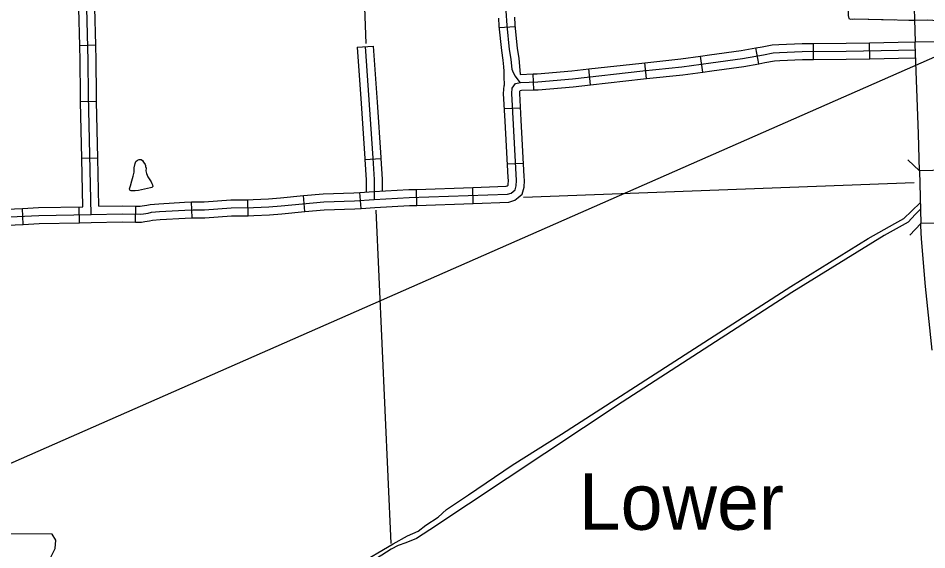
# Model space of a CAD drawing. Extents: x -5566 to 1759129, y -3726 to 731467.
# Drawn here: x -4760.4 to -4695.8, y 330.8 to 368.7 of the extents above; entities that cross this region are included whole.
import ezdxf

# ---------------------------------------------------------------- set-up
doc = ezdxf.new("R2010")
doc.units = 0
doc.layers.add('Default', color=7, linetype='Continuous')

msp = doc.modelspace()

# ---------------------------------------------------------------- linework, layer by layer
at = {"layer": 'Default'}
for p, q in [((-4726.234, 367.988), (-4725.097, 368.065)), ((-4754.916, 366.731), (-4756.055, 366.7)), ((-4736.317, 366.594), (-4735.18, 366.671)), ((-4707.76, 365.42), (-4707.965, 366.541)), ((-4703.872, 365.727), (-4703.877, 366.866)), ((-4699.854, 365.768), (-4699.875, 366.907)), ((-4711.748, 364.825), (-4711.907, 365.953)), ((-4715.75, 364.357), (-4715.869, 365.49)), ((-4723.77, 363.552), (-4723.805, 364.691)), ((-4719.731, 363.911), (-4719.858, 365.044)), ((-4754.859, 362.719), (-4755.997, 362.695)), ((-4724.71, 362.266), (-4725.848, 362.204)), ((-4754.774, 358.71), (-4755.913, 358.686)), ((-4735.774, 358.594), (-4734.637, 358.67)), ((-4724.496, 358.323), (-4725.634, 358.261)), ((-4736.053, 355.126), (-4736.136, 356.262)), ((-4732.071, 355.342), (-4732.111, 356.48)), ((-4728.064, 355.481), (-4728.103, 356.619)), ((-4748.074, 354.453), (-4748.121, 355.591)), ((-4744.085, 354.605), (-4744.102, 355.744)), ((-4740.041, 354.899), (-4740.15, 356.032)), ((-4760.08, 353.99), (-4760.132, 355.128)), ((-4756.086, 354.102), (-4756.11, 355.241)), ((-4752.102, 354.153), (-4752.077, 355.292))]:
    msp.add_line(p, q, dxfattribs=at)
for points in [[(-4813.973, 313.686), (-4397.101, 497.071), (-4397.101, 497.071)], [(-4755.259, 354.689), (-4755.438, 363.186), (-4755.457, 365.645), (-4755.557, 369.37), (-4755.723, 373.616), (-4756.249, 384.751), (-4756.683, 394.816), (-4756.724, 396.754), (-4756.875, 400.091), (-4757.762, 416.192), (-4757.786, 416.771)], [(-4736.745, 395.069), (-4735.714, 366.864)], [(-4702.309, 378.817), (-4702.105, 377.962), (-4701.846, 376.435), (-4701.707, 375.07), (-4701.5, 373.054), (-4701.416, 369.745), (-4701.392, 368.841), (-4701.36, 368.633), (-4701.242, 368.588), (-4700.92, 368.602), (-4696.883, 368.523), (-4695.733, 368.545), (-4695.387, 368.526), (-4695.122, 368.462), (-4694.828, 368.457), (-4692.797, 368.529), (-4679.95, 367.895)], [(-4756.055, 366.7), (-4756.126, 369.351), (-4756.179, 370.701)], [(-4754.916, 366.731), (-4754.987, 369.389), (-4755.041, 370.746)], [(-4696.746, 370.992), (-4696.637, 366.98)], [(-4725.82, 370.251), (-4725.677, 368.137), (-4725.505, 366.431), (-4725.402, 365.736), (-4725.359, 365.247), (-4725.333, 365.035), (-4725.24, 364.802), (-4725.094, 364.527), (-4724.752, 364.091)], [(-4726.283, 368.658), (-4726.244, 368.089), (-4726.071, 366.36), (-4725.968, 365.67), (-4725.926, 365.188), (-4725.89, 364.892), (-4725.894, 364.522), (-4725.87, 363.877)], [(-4725.146, 368.735), (-4725.109, 368.185), (-4724.94, 366.501), (-4724.836, 365.803), (-4724.736, 364.662)], [(-4701.095, 368.594), (-4700.92, 368.602), (-4698.088, 368.546)], [(-4697.086, 368.527), (-4696.662, 368.518)], [(-4755.997, 362.695), (-4756.008, 363.178), (-4756.026, 365.636), (-4756.055, 366.7)], [(-4754.859, 362.719), (-4754.868, 363.194), (-4754.887, 365.655), (-4754.916, 366.731)], [(-4736.317, 366.594), (-4736.045, 362.594)], [(-4735.749, 366.633), (-4735.21, 358.703), (-4735.107, 357.175), (-4735.107, 355.766)], [(-4735.18, 366.671), (-4734.909, 362.671)], [(-4711.907, 365.953), (-4711.254, 366.045), (-4709.013, 366.349), (-4707.965, 366.541)], [(-4707.965, 366.541), (-4707.524, 366.621), (-4706.802, 366.753), (-4706.324, 366.794), (-4704.679, 366.862), (-4703.877, 366.866)], [(-4703.877, 366.866), (-4701.548, 366.876), (-4699.875, 366.907)], [(-4699.875, 366.907), (-4697.842, 366.944), (-4696.637, 366.98)], [(-4696.637, 366.98), (-4694.739, 367.01), (-4694.736, 366.86), (-4694.497, 360.49), (-4694.427, 357.853)], [(-4694.427, 357.853), (-4696.325, 357.802), (-4696.395, 360.429), (-4696.634, 366.809), (-4696.637, 366.98)], [(-4696.637, 366.965), (-4696.637, 366.965)], [(-4724.712, 364.093), (-4723.485, 364.131), (-4721.012, 364.341), (-4716.012, 364.902), (-4713.24, 365.191), (-4711.176, 365.481), (-4708.923, 365.786), (-4707.421, 366.061), (-4706.727, 366.188), (-4706.287, 366.225), (-4704.666, 366.293), (-4701.541, 366.306), (-4697.828, 366.375), (-4696.62, 366.41)], [(-4715.869, 365.49), (-4713.309, 365.757), (-4711.907, 365.953)], [(-4699.854, 365.768), (-4697.814, 365.806), (-4696.604, 365.841)], [(-4719.858, 365.044), (-4716.073, 365.468), (-4715.869, 365.49)], [(-4711.748, 364.825), (-4711.098, 364.916), (-4708.833, 365.224), (-4707.76, 365.42)], [(-4707.76, 365.42), (-4707.319, 365.501), (-4706.651, 365.622), (-4706.251, 365.657), (-4704.653, 365.723), (-4703.872, 365.727)], [(-4703.872, 365.727), (-4701.535, 365.737), (-4699.854, 365.768)], [(-4724.736, 364.662), (-4723.805, 364.691)], [(-4723.805, 364.691), (-4723.518, 364.699), (-4721.068, 364.908), (-4719.858, 365.044)], [(-4715.75, 364.357), (-4713.171, 364.626), (-4711.748, 364.825)], [(-4764.628, 354.352), (-4758.968, 354.611), (-4755.259, 354.689), (-4753.046, 354.743), (-4751.719, 354.714), (-4751.531, 354.749), (-4751.188, 354.797), (-4750.966, 354.845), (-4750.389, 354.893), (-4748.588, 355.002), (-4747.999, 355.026), (-4747.536, 355.014), (-4747.194, 355.014), (-4745.297, 355.156), (-4743.698, 355.18), (-4742.606, 355.235), (-4741.735, 355.307), (-4738.708, 355.6), (-4736.524, 355.663), (-4735.107, 355.766), (-4732.622, 355.893), (-4725.638, 356.135), (-4725.382, 356.219), (-4725.234, 356.331), (-4725.096, 356.455), (-4725.016, 356.724), (-4725.001, 357.104), (-4725.336, 363.295), (-4725.312, 363.671), (-4725.06, 364.007), (-4724.712, 364.093)], [(-4723.77, 363.552), (-4723.452, 363.562), (-4720.956, 363.774), (-4719.731, 363.911)], [(-4719.731, 363.911), (-4715.95, 364.336), (-4715.75, 364.357)], [(-4725.801, 361.338), (-4725.907, 363.298), (-4725.87, 363.877)], [(-4724.663, 361.4), (-4724.766, 363.292), (-4724.755, 363.465), (-4724.727, 363.503), (-4724.635, 363.525), (-4723.77, 363.552)], [(-4755.913, 358.686), (-4755.997, 362.695)], [(-4754.774, 358.71), (-4754.859, 362.719)], [(-4734.909, 362.671), (-4734.642, 358.742), (-4734.637, 358.67)], [(-4736.045, 362.594), (-4735.778, 358.665), (-4735.774, 358.593)], [(-4725.583, 357.334), (-4725.801, 361.338)], [(-4724.446, 357.396), (-4724.663, 361.4)], [(-4755.841, 355.246), (-4755.913, 358.686)], [(-4754.702, 355.272), (-4754.774, 358.71)], [(-4752.249, 357.425), (-4752.189, 357.696), (-4752.183, 358.014), (-4752.129, 358.327), (-4752.069, 358.471), (-4751.942, 358.562), (-4751.828, 358.604), (-4751.696, 358.6), (-4751.597, 358.532), (-4751.525, 358.415), (-4751.418, 358.256), (-4751.373, 358.17), (-4751.38, 358.105), (-4751.347, 357.985), (-4751.365, 357.798), (-4751.317, 357.611), (-4751.215, 357.371), (-4750.987, 357.004)], [(-4735.774, 358.594), (-4735.677, 357.156), (-4735.677, 356.296)], [(-4734.637, 358.67), (-4734.538, 357.194), (-4734.538, 356.365)], [(-4696.325, 357.802), (-4697.151, 358.586)], [(-4696.325, 357.802), (-4696.225, 354.063)], [(-4750.987, 357.004), (-4750.927, 356.896), (-4750.896, 356.8), (-4750.866, 356.685), (-4750.921, 356.613), (-4751.023, 356.577), (-4751.87, 356.403), (-4752.117, 356.367), (-4752.303, 356.367), (-4752.411, 356.379), (-4752.495, 356.421), (-4752.514, 356.505), (-4752.459, 356.739), (-4752.345, 357.094), (-4752.249, 357.425)], [(-4728.103, 356.619), (-4725.739, 356.702), (-4725.649, 356.731), (-4725.596, 356.771), (-4725.583, 356.818), (-4725.571, 357.1), (-4725.583, 357.334)], [(-4728.064, 355.481), (-4725.537, 355.569), (-4725.115, 355.708), (-4724.872, 355.89), (-4724.595, 356.139), (-4724.45, 356.63), (-4724.43, 357.108), (-4724.446, 357.396)], [(-4724.498, 355.914), (-4696.702, 356.959)], [(-4740.15, 356.032), (-4738.744, 356.168), (-4736.553, 356.232), (-4736.136, 356.262)], [(-4736.136, 356.262), (-4735.142, 356.334), (-4732.646, 356.462), (-4732.111, 356.48)], [(-4732.111, 356.48), (-4728.103, 356.619)], [(-4752.077, 355.292), (-4751.765, 355.285), (-4751.622, 355.311), (-4751.288, 355.358), (-4751.05, 355.41), (-4750.429, 355.461), (-4748.617, 355.57), (-4748.121, 355.591)], [(-4748.121, 355.591), (-4748.003, 355.596), (-4747.529, 355.583), (-4747.215, 355.583), (-4745.323, 355.726), (-4744.102, 355.744)], [(-4744.102, 355.744), (-4743.717, 355.749), (-4742.644, 355.804), (-4741.786, 355.874), (-4740.15, 356.032)], [(-4730.561, 333.153), (-4729.978, 333.705), (-4728.415, 334.753), (-4725.297, 336.847), (-4721.788, 339.061), (-4712.673, 344.941), (-4705.479, 349.572), (-4699.966, 352.976), (-4698.087, 354.045), (-4697.444, 354.414), (-4696.906, 354.934), (-4696.264, 355.539)], [(-4764.138, 354.944), (-4760.132, 355.128)], [(-4760.132, 355.128), (-4758.987, 355.18), (-4755.841, 355.246)], [(-4754.702, 355.272), (-4753.046, 355.313), (-4752.077, 355.292)], [(-4696.252, 355.061), (-4696.632, 354.686), (-4697.139, 354.156), (-4698.831, 353.208), (-4705.395, 349.146), (-4717.477, 341.348), (-4731.156, 332.251), (-4732.102, 331.642), (-4732.867, 331.328), (-4733.4, 331.136), (-4733.902, 330.892), (-4734.572, 330.459), (-4742.996, 325.302), (-4744.672, 324.236), (-4746.615, 322.956), (-4748.105, 322.025), (-4751.473, 319.9), (-4753.098, 318.821)], [(-4744.085, 354.605), (-4743.68, 354.611), (-4742.568, 354.667), (-4741.685, 354.739), (-4740.041, 354.899)], [(-4740.041, 354.899), (-4738.672, 355.031), (-4736.495, 355.094), (-4736.053, 355.126)], [(-4736.053, 355.126), (-4735.072, 355.197), (-4732.598, 355.324), (-4732.071, 355.342)], [(-4735, 354.998), (-4733.937, 331.274)], [(-4732.071, 355.342), (-4728.064, 355.481)], [(-4752.102, 354.153), (-4751.673, 354.144), (-4751.44, 354.187), (-4751.088, 354.236), (-4750.881, 354.281), (-4750.348, 354.325), (-4748.559, 354.433), (-4748.074, 354.453)], [(-4748.074, 354.453), (-4747.995, 354.456), (-4747.544, 354.444), (-4747.172, 354.444), (-4745.271, 354.587), (-4744.085, 354.605)], [(-4764.086, 353.806), (-4760.08, 353.99)], [(-4760.08, 353.99), (-4758.949, 354.041), (-4756.086, 354.102)], [(-4756.086, 354.102), (-4755.247, 354.119), (-4753.045, 354.173), (-4752.102, 354.153)], [(-4697.006, 353.23), (-4696.225, 354.06)], [(-4695.435, 345.027), (-4695.901, 349.575), (-4696.18, 352.957), (-4696.22, 353.887), (-4696.225, 354.063), (-4694.327, 354.113)], [(-4754.128, 318.759), (-4750.752, 320.921), (-4747.973, 322.677), (-4744.417, 324.862), (-4740.467, 327.31), (-4736.357, 329.733), (-4733.777, 331.269), (-4732.753, 331.827), (-4731.996, 332.156), (-4731.432, 332.577), (-4730.561, 333.153)]]:
    msp.add_lwpolyline(points, dxfattribs=at)
msp.add_lwpolyline([(-4769.573, 331.966), (-4768.995, 328.112), (-4769.252, 322.266), (-4768.738, 321.945), (-4767.775, 321.945), (-4767.775, 319.889), (-4759.681, 319.889), (-4759.295, 320.724), (-4759.424, 322.073), (-4759.231, 323.615), (-4758.524, 324.836), (-4758.075, 325.735), (-4757.432, 326.699), (-4757.047, 327.726), (-4756.726, 328.561), (-4756.147, 329.268), (-4756.019, 329.718), (-4756.276, 330.039), (-4758.267, 330.039), (-4757.818, 330.938), (-4757.753, 331.516), (-4758.02, 331.96)], close=True, dxfattribs=at)

# ---------------------------------------------------------------- texts
msp.add_text('Lower', height=4.0097, dxfattribs=at).set_placement((-4720.568, 332.262))

doc.saveas('drawing.dxf')
